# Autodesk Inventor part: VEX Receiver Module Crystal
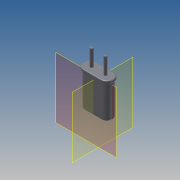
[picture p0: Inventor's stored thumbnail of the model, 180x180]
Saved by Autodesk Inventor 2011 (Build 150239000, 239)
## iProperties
Created: 2007-08
Part Number: VEX Receiver Module Crystal
Material: Steel
Document SubType Name: Modeling
Designer: Tyler
Density: 7.85 g/cm^3
Author: Tyler
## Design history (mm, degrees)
feature "Base1"
workplane "Work Plane1"
workplane "Work Plane2"
body "Solid1"
